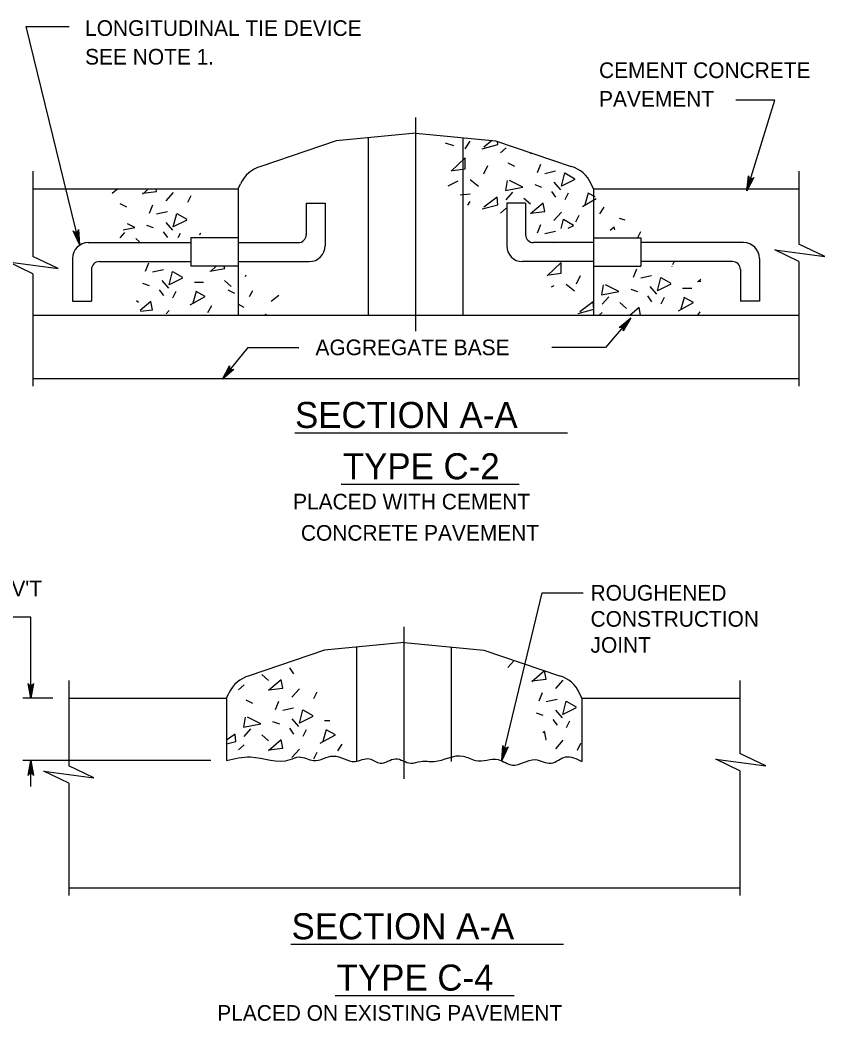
# Model space of a CAD drawing. Extents: x -28.1 to -20.9, y 67 to 77.1.
# Drawn here: x -24.167 to -21.078, y 73.056 to 76.898 of the extents above; entities that cross this region are included whole.
import ezdxf

# ---------------------------------------------------------------- set-up
doc = ezdxf.new("R2010")
doc.units = 0
for name, color, linetype in [('DETL-DIMS', 7, 'Continuous'), ('DETL-LINE', 7, 'Continuous'), ('DETL-NOTE', 7, 'Continuous'), ('DETL-PATT', 7, 'Continuous'), ('DETL-TITL', 7, 'Continuous')]:
    doc.layers.add(name, color=color, linetype=linetype)

msp = doc.modelspace()

# ---------------------------------------------------------------- linework, layer by layer
at = {"layer": 'DETL-DIMS'}
for p, q in [((-23.9392, 76.0358), (-24.143, 76.8726)), ((-24.143, 76.8726), (-23.978, 76.8726)), ((-21.27, 76.5897), (-21.4201, 76.5897)), ((-21.3779, 76.2423), (-21.27, 76.5897)), ((-22.6479, 75.704), (-22.6479, 76.5236)), ((-21.8236, 75.7542), (-21.9201, 75.6414)), ((-23.3904, 75.5195), (-23.2918, 75.6415)), ((-23.2918, 75.6415), (-23.0972, 75.6415)), ((-21.9201, 75.6414), (-22.1263, 75.6414)), ((-22.3176, 74.0556), (-22.1627, 74.6993)), ((-22.1627, 74.6993), (-22.0064, 74.6993)), ((-24.1259, 74.6053), (-24.2583, 74.6053)), ((-24.1259, 74.2946), (-24.1259, 74.6053)), ((-22.6926, 73.986), (-22.6926, 74.5687)), ((-24.041, 74.2946), (-24.1562, 74.2946)), ((-23.435, 74.0552), (-24.1562, 74.0552)), ((-24.1259, 73.9562), (-24.1259, 74.0552))]:
    msp.add_line(p, q, dxfattribs=at)
for points in [[(-21.3779, 76.2423), (-21.3713, 76.2994), (-21.3697, 76.2944), (-21.3667, 76.2911), (-21.3633, 76.2893), (-21.3595, 76.2888), (-21.3552, 76.2899), (-21.351, 76.2931), (-21.3779, 76.2423), (-21.3552, 76.2899), (-21.3595, 76.2888), (-21.3779, 76.2423), (-21.3633, 76.2893), (-21.3667, 76.2911), (-21.3779, 76.2423), (-21.3697, 76.2944)], [(-23.9392, 76.0358), (-23.9629, 76.0882), (-23.9589, 76.0847), (-23.9547, 76.0834), (-23.9509, 76.0837), (-23.9473, 76.0852), (-23.9442, 76.0883), (-23.9423, 76.0932), (-23.9392, 76.0358), (-23.9442, 76.0883), (-23.9473, 76.0852), (-23.9392, 76.0358), (-23.9509, 76.0837), (-23.9547, 76.0834), (-23.9392, 76.0358), (-23.9589, 76.0847)], [(-21.8236, 75.7542), (-21.8523, 75.7044), (-21.8517, 75.7097), (-21.8531, 75.7138), (-21.8556, 75.7168), (-21.8589, 75.7188), (-21.8632, 75.7195), (-21.8684, 75.7182), (-21.8236, 75.7542), (-21.8632, 75.7195), (-21.8589, 75.7188), (-21.8236, 75.7542), (-21.8556, 75.7168), (-21.8531, 75.7138), (-21.8236, 75.7542), (-21.8517, 75.7097)], [(-23.3904, 75.5195), (-23.3631, 75.5701), (-23.3635, 75.5648), (-23.362, 75.5607), (-23.3594, 75.5578), (-23.3561, 75.5559), (-23.3517, 75.5553), (-23.3466, 75.5568), (-23.3904, 75.5195), (-23.3517, 75.5553), (-23.3561, 75.5559), (-23.3904, 75.5195), (-23.3594, 75.5578), (-23.362, 75.5607), (-23.3904, 75.5195), (-23.3635, 75.5648)], [(-24.1259, 74.2946), (-24.1365, 74.3511), (-24.1335, 74.3468), (-24.1297, 74.3445), (-24.1259, 74.3439), (-24.1221, 74.3445), (-24.1183, 74.3468), (-24.1153, 74.3511), (-24.1259, 74.2946), (-24.1183, 74.3468), (-24.1221, 74.3445), (-24.1259, 74.2946), (-24.1259, 74.3439), (-24.1297, 74.3445), (-24.1259, 74.2946), (-24.1335, 74.3468)], [(-22.3176, 74.0556), (-22.3146, 74.1131), (-22.3127, 74.1081), (-22.3096, 74.105), (-22.306, 74.1035), (-22.3022, 74.1033), (-22.298, 74.1046), (-22.294, 74.1081), (-22.3176, 74.0556), (-22.298, 74.1046), (-22.3022, 74.1033), (-22.3176, 74.0556), (-22.306, 74.1035), (-22.3096, 74.105), (-22.3176, 74.0556), (-22.3127, 74.1081)], [(-24.1259, 74.0552), (-24.1153, 73.9987), (-24.1183, 74.0031), (-24.1221, 74.0053), (-24.1259, 74.006), (-24.1297, 74.0053), (-24.1335, 74.0031), (-24.1365, 73.9987), (-24.1259, 74.0552), (-24.1335, 74.0031), (-24.1297, 74.0053), (-24.1259, 74.0552), (-24.1259, 74.006), (-24.1221, 74.0053), (-24.1259, 74.0552), (-24.1183, 74.0031)]]:
    msp.add_lwpolyline(points, dxfattribs=at)
at = {"layer": 'DETL-LINE'}
for p, q in [((-22.6479, 76.463), (-22.9535, 76.4335)), ((-22.6479, 76.463), (-22.3423, 76.4335)), ((-22.9535, 76.4335), (-23.2435, 76.3355)), ((-22.8297, 75.7646), (-22.8297, 76.4455)), ((-22.4661, 75.7646), (-22.4661, 76.4455)), ((-22.3423, 76.4335), (-22.0524, 76.3355)), ((-24.1175, 76.3178), (-24.1175, 75.9902)), ((-21.1783, 76.3178), (-21.1783, 76.0374)), ((-23.3296, 76.2495), (-23.3207, 76.2691)), ((-21.9662, 76.2495), (-21.9751, 76.2691)), ((-24.1175, 76.2495), (-23.3296, 76.2495)), ((-23.3296, 76.2495), (-23.3296, 76.1283)), ((-23.3296, 76.2495), (-23.3296, 75.7646)), ((-21.9662, 76.2495), (-21.1783, 76.2495)), ((-21.9662, 76.2495), (-21.9662, 75.7646)), ((-23.069, 76.1949), (-23.069, 76.0737)), ((-23.069, 76.1949), (-22.9963, 76.1949)), ((-22.9963, 76.1949), (-22.9963, 76.0313)), ((-22.2995, 76.1949), (-22.2995, 76.0313)), ((-22.2268, 76.1949), (-22.2995, 76.1949)), ((-22.2268, 76.1949), (-22.2268, 76.0737)), ((-23.3296, 76.0798), (-23.3296, 75.9343)), ((-23.3296, 76.0798), (-23.3296, 75.9343)), ((-21.9662, 76.0798), (-21.9662, 75.9343)), ((-23.9054, 76.0434), (-23.5114, 76.0434)), ((-23.3296, 76.0616), (-23.5114, 76.0616)), ((-23.5114, 76.0616), (-23.5114, 75.9525)), ((-23.3296, 76.0434), (-23.0993, 76.0434)), ((-21.9662, 76.0434), (-22.1965, 76.0434)), ((-21.9662, 76.0616), (-21.7844, 76.0616)), ((-21.7844, 76.0616), (-21.7844, 75.9525)), ((-21.3904, 76.0434), (-21.7844, 76.0434)), ((-23.966, 75.9828), (-23.966, 75.8192)), ((-23.863, 75.9707), (-23.5114, 75.9707)), ((-23.3296, 75.9525), (-23.5114, 75.9525)), ((-23.3296, 75.9707), (-23.0569, 75.9707)), ((-21.9662, 75.9707), (-22.2389, 75.9707)), ((-21.9662, 75.9525), (-21.7844, 75.9525)), ((-21.4329, 75.9707), (-21.7844, 75.9707)), ((-21.3298, 75.9828), (-21.3298, 75.8192)), ((-21.1783, 75.9708), (-21.1783, 75.4923)), ((-24.1175, 75.9236), (-24.1175, 75.4923)), ((-23.8933, 75.9404), (-23.8933, 75.8192)), ((-21.4025, 75.9404), (-21.4025, 75.8192)), ((-21.9662, 75.8859), (-21.9662, 75.7646)), ((-23.966, 75.8192), (-23.8933, 75.8192)), ((-21.3298, 75.8192), (-21.4025, 75.8192)), ((-24.1175, 75.7646), (-21.1783, 75.7646)), ((-24.1175, 75.5222), (-21.1783, 75.5222)), ((-22.6926, 74.5081), (-22.9982, 74.4787)), ((-22.6926, 74.5081), (-22.3871, 74.4787)), ((-22.9982, 74.4787), (-23.2882, 74.3807)), ((-22.8745, 74.0522), (-22.8745, 74.4906)), ((-22.5108, 74.0522), (-22.5108, 74.4906)), ((-22.3871, 74.4787), (-22.0971, 74.3807)), ((-23.9804, 74.3629), (-23.9804, 74.0353)), ((-21.4049, 74.3629), (-21.4049, 74.0825)), ((-23.3744, 74.2946), (-23.3655, 74.3142)), ((-22.0109, 74.2946), (-22.0198, 74.3142)), ((-23.9804, 74.2946), (-23.3744, 74.2946)), ((-23.3744, 74.2946), (-23.3744, 74.0552)), ((-22.0109, 74.2946), (-21.4049, 74.2946)), ((-22.0109, 74.2946), (-22.0109, 74.0522)), ((-21.4049, 74.016), (-21.4049, 73.5374)), ((-23.9804, 73.9687), (-23.9804, 73.5374)), ((-23.9804, 73.5674), (-21.4049, 73.5674))]:
    msp.add_line(p, q, dxfattribs=at)
for points in [[(-22.0091, 76.1825), (-21.9558, 76.2122)], [(-21.1783, 75.9708), (-21.2702, 76.0158), (-21.078, 75.9896), (-21.1783, 76.0374)], [(-24.1175, 75.9236), (-24.2126, 75.9701), (-24.0204, 75.944), (-24.1175, 75.9902)], [(-21.4049, 74.016), (-21.4967, 74.0609), (-21.3045, 74.0348), (-21.4049, 74.0825)], [(-23.9804, 73.9687), (-24.0755, 74.0153), (-23.8833, 73.9891), (-23.9804, 74.0353)]]:
    msp.add_lwpolyline(points, dxfattribs=at)
for centre, radius, start, end in [((-23.2104, 76.2189), 0.1212, 105.8409, 155.576), ((-22.0854, 76.2189), 0.1212, 24.424, 74.1591), ((-23.0993, 76.0737), 0.0303, 270, 0), ((-22.1965, 76.0737), 0.0303, 180, 270), ((-23.9054, 75.9828), 0.0606, 90, 180), ((-23.0569, 76.0313), 0.0606, 270, 0), ((-22.2389, 76.0313), 0.0606, 180, 270), ((-21.3904, 75.9828), 0.0606, 0, 90), ((-23.863, 75.9404), 0.0303, 90, 180), ((-21.4328, 75.9404), 0.0303, 0, 90), ((-23.2551, 74.2641), 0.1212, 105.8409, 155.576), ((-22.1302, 74.2641), 0.1212, 24.424, 74.1591)]:
    msp.add_arc(centre, radius, start, end, dxfattribs=at)
msp.add_spline([(-23.3744, 74.0552), (-23.2822, 74.0694), (-23.1302, 74.059), (-23.0957, 74.0694), (-23.0404, 74.0556), (-22.9645, 74.0729), (-22.8816, 74.0521), (-22.8263, 74.0625), (-22.7849, 74.0452), (-22.7261, 74.0625), (-22.6674, 74.0452), (-22.6294, 74.0521), (-22.5776, 74.0521), (-22.4671, 74.0729), (-22.4187, 74.0556), (-22.3324, 74.059), (-22.2771, 74.0383), (-22.1908, 74.059), (-22.1286, 74.0452), (-22.0734, 74.0694), (-22.0109, 74.0522)], degree=3, dxfattribs=at)
at = {"layer": 'DETL-PATT'}
for p, q in [((-22.5354, 76.4264), (-22.5033, 76.4168)), ((-22.4584, 76.404), (-22.4391, 76.4329)), ((-22.3236, 76.3879), (-22.3012, 76.4072)), ((-22.3878, 76.3077), (-22.3717, 76.3398)), ((-22.2948, 76.3494), (-22.2691, 76.3366)), ((-22.1696, 76.343), (-22.1824, 76.3109)), ((-22.1173, 76.36), (-22.1182, 76.359)), ((-22.1118, 76.3173), (-22.1535, 76.3077)), ((-22.4873, 76.2788), (-22.5258, 76.2596)), ((-22.4391, 76.2852), (-22.4071, 76.2596)), ((-22.192, 76.266), (-22.1664, 76.2564)), ((-22.1182, 76.2756), (-22.0926, 76.2467)), ((-23.8131, 76.2327), (-23.7918, 76.251)), ((-23.5789, 76.2359), (-23.6077, 76.2038)), ((-23.5115, 76.223), (-23.5243, 76.1974)), ((-22.4777, 76.2275), (-22.4391, 76.2307)), ((-22.3012, 76.2082), (-22.2755, 76.2371)), ((-22.1279, 76.2403), (-22.1118, 76.2178)), ((-22.0637, 76.2339), (-22.0765, 76.2082)), ((-23.7843, 76.1942), (-23.7586, 76.1813)), ((-23.6591, 76.1878), (-23.6719, 76.1557)), ((-22.449, 76.187), (-22.4391, 76.2018)), ((-22.2338, 76.2146), (-22.2081, 76.1922)), ((-23.6013, 76.1621), (-23.6431, 76.1524)), ((-22.3236, 76.1569), (-22.3012, 76.1761)), ((-22.0894, 76.1601), (-22.1182, 76.128)), ((-22.022, 76.1472), (-22.0348, 76.1216)), ((-21.9417, 76.1537), (-21.9257, 76.1793)), ((-23.6816, 76.1107), (-23.6559, 76.1011)), ((-23.6077, 76.1204), (-23.5821, 76.0915)), ((-22.1696, 76.1119), (-22.1824, 76.0798)), ((-21.8679, 76.1376), (-21.8455, 76.1312)), ((-23.7823, 76.0624), (-23.765, 76.0819)), ((-23.6174, 76.0851), (-23.6013, 76.0626)), ((-23.5532, 76.0787), (-23.5615, 76.062)), ((-22.1118, 76.0863), (-22.1535, 76.0766)), ((-21.7959, 76.0635), (-21.7845, 76.0863)), ((-23.7233, 76.0594), (-23.7088, 76.0467)), ((-22.1182, 76.0445), (-22.1177, 76.044)), ((-23.6746, 75.9652), (-23.6875, 75.9332)), ((-21.6658, 75.9525), (-21.6663, 75.9516)), ((-21.6567, 75.9708), (-21.6631, 75.9579)), ((-23.6169, 75.9396), (-23.6586, 75.9299)), ((-23.3024, 75.9139), (-23.2994, 75.9199)), ((-22.0317, 75.885), (-22.0157, 75.9171)), ((-21.8011, 75.9419), (-21.8139, 75.9099)), ((-21.7433, 75.9163), (-21.785, 75.9067)), ((-23.6971, 75.8882), (-23.6714, 75.8786)), ((-23.6233, 75.8978), (-23.5976, 75.869)), ((-23.4981, 75.8914), (-23.4628, 75.8914)), ((-23.3826, 75.8978), (-23.3569, 75.8754)), ((-22.1188, 75.8778), (-22.1284, 75.873)), ((-22.0706, 75.8842), (-22.0386, 75.8585)), ((-23.6329, 75.8625), (-23.6169, 75.8401)), ((-23.5687, 75.8561), (-23.5816, 75.8304)), ((-23.3697, 75.8625), (-23.3441, 75.8497)), ((-23.2863, 75.8369), (-23.2735, 75.8593)), ((-23.174, 75.8401), (-23.2029, 75.8176)), ((-21.8235, 75.8649), (-21.7979, 75.8553)), ((-21.7594, 75.8393), (-21.7433, 75.8168)), ((-21.7497, 75.8745), (-21.7241, 75.8457)), ((-21.6246, 75.8681), (-21.5893, 75.8681)), ((-23.7205, 75.8209), (-23.7131, 75.8144)), ((-23.4468, 75.7759), (-23.4307, 75.8016)), ((-23.3312, 75.808), (-23.3088, 75.7952)), ((-21.9327, 75.8072), (-21.907, 75.836)), ((-21.8653, 75.8136), (-21.8396, 75.7911)), ((-21.6952, 75.8328), (-21.708, 75.8072)), ((-23.5944, 75.7823), (-23.6059, 75.7696)), ((-23.527, 75.7695), (-23.5271, 75.7692)), ((-21.9446, 75.7648), (-21.9327, 75.7751)), ((-21.5656, 75.7648), (-21.5572, 75.7783)), ((-22.2954, 74.4124), (-22.2725, 74.4383)), ((-23.2393, 74.3853), (-23.2136, 74.3628)), ((-23.1334, 74.4109), (-23.1174, 74.3885)), ((-23.3292, 74.3275), (-23.3067, 74.3468)), ((-22.0836, 74.3643), (-22.1125, 74.3322)), ((-23.0949, 74.3307), (-23.1238, 74.2986)), ((-23.0275, 74.3179), (-23.0404, 74.2922)), ((-22.1639, 74.3161), (-22.1767, 74.284)), ((-22.0275, 74.3289), (-22.0291, 74.3258)), ((-23.3003, 74.289), (-23.2746, 74.2762)), ((-23.1751, 74.2826), (-23.188, 74.2505)), ((-22.1061, 74.2905), (-22.1478, 74.2808)), ((-23.1174, 74.2569), (-23.1591, 74.2473)), ((-22.1863, 74.2391), (-22.1606, 74.2295)), ((-22.1125, 74.2487), (-22.0869, 74.2199)), ((-23.1976, 74.2056), (-23.1719, 74.1959)), ((-23.1238, 74.2152), (-23.0981, 74.1863)), ((-22.9986, 74.2088), (-22.9778, 74.2088)), ((-22.1221, 74.2134), (-22.1061, 74.191)), ((-22.058, 74.207), (-22.0708, 74.1813)), ((-23.3067, 74.1478), (-23.281, 74.1767)), ((-23.2393, 74.1542), (-23.2136, 74.1318)), ((-23.1334, 74.1799), (-23.1174, 74.1574)), ((-23.0693, 74.1735), (-23.0821, 74.1478)), ((-23.3292, 74.0964), (-23.3067, 74.1157)), ((-22.9473, 74.0932), (-22.9312, 74.1189)), ((-22.0836, 74.1332), (-22.1125, 74.1011)), ((-22.0162, 74.1204), (-22.0291, 74.0947)), ((-23.0949, 74.0996), (-23.1238, 74.0676)), ((-23.0275, 74.0868), (-23.0404, 74.0611))]:
    msp.add_line(p, q, dxfattribs=at)
for points in [[(-22.3942, 76.404), (-22.3332, 76.42), (-22.3345, 76.431)], [(-22.3552, 76.4348), (-22.3878, 76.4104)], [(-22.2081, 76.3879), (-22.2041, 76.3884)], [(-22.2039, 76.3883), (-22.2081, 76.3847)], [(-22.5065, 76.3205), (-22.4584, 76.3269), (-22.4584, 76.3687), (-22.513, 76.3173)], [(-22.038, 76.2852), (-22.0894, 76.2596), (-22.0765, 76.3109), (-22.038, 76.2884)], [(-22.298, 76.282), (-22.3044, 76.2435), (-22.237, 76.2564), (-22.2883, 76.282)], [(-23.674, 76.25), (-23.6976, 76.2295)], [(-23.6976, 76.2327), (-23.6431, 76.2391), (-23.6452, 76.2497)], [(-21.9604, 76.2196), (-21.9867, 76.2339), (-21.9995, 76.189)], [(-22.3942, 76.1729), (-22.3332, 76.189), (-22.3365, 76.2178), (-22.3878, 76.1793)], [(-22.2081, 76.1569), (-22.1535, 76.1633), (-22.16, 76.1954), (-22.2081, 76.1537)], [(-23.5275, 76.13), (-23.5789, 76.1043), (-23.566, 76.1557), (-23.5275, 76.1332)], [(-23.7716, 76.0925), (-23.7265, 76.1011), (-23.7546, 76.1152)], [(-22.0909, 76.0972), (-22.0819, 76.1332), (-22.0433, 76.1107)], [(-22.0433, 76.1075), (-22.0642, 76.0971)], [(-23.4738, 76.0774), (-23.4762, 76.0787), (-23.4781, 76.072)], [(-21.8838, 76.0922), (-21.8872, 76.1023), (-21.9022, 76.0894)], [(-22.138, 75.9195), (-22.0899, 75.9259), (-22.0899, 75.9676), (-22.1445, 75.9163)], [(-23.543, 75.9075), (-23.5944, 75.8818), (-23.5816, 75.9332), (-23.543, 75.9107)], [(-23.4385, 75.9342), (-23.3807, 75.9438), (-23.3833, 75.9514)], [(-23.4152, 75.9514), (-23.4353, 75.9342)], [(-21.9294, 75.881), (-21.9359, 75.8425), (-21.8685, 75.8553), (-21.9198, 75.881)], [(-21.6695, 75.8842), (-21.7209, 75.8585), (-21.708, 75.9099), (-21.6695, 75.8874)], [(-21.5668, 75.8938), (-21.5549, 75.8958)], [(-21.5546, 75.9015), (-21.5636, 75.8938)], [(-23.5142, 75.8048), (-23.4564, 75.8369), (-23.4917, 75.8561), (-23.5045, 75.8112)], [(-23.7047, 75.7801), (-23.6586, 75.7855), (-23.665, 75.8176), (-23.7056, 75.7824)], [(-22.0257, 75.7719), (-21.9647, 75.7879), (-21.968, 75.8168), (-22.0193, 75.7783)], [(-21.6406, 75.7815), (-21.5829, 75.8136), (-21.6182, 75.8328), (-21.631, 75.7879)], [(-23.2262, 75.7678), (-23.2253, 75.7695), (-23.2226, 75.7678)], [(-21.7856, 75.7648), (-21.7915, 75.7943), (-21.8255, 75.7648)], [(-22.2024, 74.3611), (-22.1478, 74.3675), (-22.1542, 74.3995)], [(-22.1543, 74.3995), (-22.2024, 74.3579)], [(-23.2136, 74.3275), (-23.1591, 74.3339), (-23.1655, 74.366), (-23.2136, 74.3243)], [(-22.0323, 74.2584), (-22.0836, 74.2327), (-22.0708, 74.284), (-22.0323, 74.2616)], [(-23.0436, 74.2248), (-23.0949, 74.1991), (-23.0821, 74.2505), (-23.0436, 74.228)], [(-23.3035, 74.2216), (-23.3099, 74.1831), (-23.2425, 74.1959), (-23.2939, 74.2216)], [(-23.3744, 74.1192), (-23.3388, 74.1285), (-23.342, 74.1574), (-23.3744, 74.1332)], [(-23.0147, 74.1221), (-22.9569, 74.1542), (-22.9922, 74.1735), (-23.0051, 74.1285)], [(-22.15, 74.1361), (-22.1478, 74.1364), (-22.1542, 74.1685), (-22.1613, 74.1624)], [(-23.2136, 74.0964), (-23.1591, 74.1029), (-23.1655, 74.135), (-23.2136, 74.0932)]]:
    msp.add_lwpolyline(points, dxfattribs=at)
at = {"layer": 'DETL-TITL'}
for p, q in [((-23.1125, 75.3135), (-22.0659, 75.3135)), ((-22.9341, 75.1165), (-22.2521, 75.1165)), ((-23.1281, 73.351), (-22.0814, 73.351)), ((-22.9576, 73.154), (-22.2703, 73.154))]:
    msp.add_line(p, q, dxfattribs=at)

# ---------------------------------------------------------------- texts
at = {"layer": 'DETL-NOTE'}
for s, p in [('LONGITUDINAL TIE DEVICE', (-23.9174, 76.8369)), ('SEE NOTE 1.', (-23.9174, 76.7269)), ('CEMENT CONCRETE', (-21.945, 76.6752)), ('PAVEMENT', (-21.945, 76.5652)), ('AGGREGATE BASE', (-23.0332, 75.6114)), ('PLACED WITH CEMENT', (-23.1192, 75.0194)), ('CONCRETE PAVEMENT', (-23.0892, 74.8994)), ('4" (MIN.) EXISTING PAV\'T', (-25.0448, 74.6859)), ('ROUGHENED', (-21.9777, 74.6693)), ('CONSTRUCTION', (-21.9777, 74.5693)), ('JOINT', (-21.9777, 74.4693)), ('PLACED ON EXISTING PAVEMENT', (-23.4103, 73.0569))]:
    msp.add_text(s, height=0.06, dxfattribs=at).set_placement(p)
at = {"layer": 'DETL-TITL'}
for s, p in [('SECTION A-A', (-23.1118, 75.3321)), ('TYPE C-2', (-22.9283, 75.1351)), ('SECTION A-A', (-23.1252, 73.3696)), ('TYPE C-4', (-22.952, 73.1726))]:
    msp.add_text(s, height=0.1, dxfattribs=at).set_placement(p)

doc.saveas('drawing.dxf')
